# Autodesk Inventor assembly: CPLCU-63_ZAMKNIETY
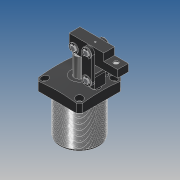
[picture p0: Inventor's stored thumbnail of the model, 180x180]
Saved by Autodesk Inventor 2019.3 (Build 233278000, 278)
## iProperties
Created: 2010-03
Part Number: CPLCU-63_ZAMKNIETY
Material: Ogólny
Document SubType Name: Assembly
Designer: CADENGINEERING4
Sending System: PRO/ENGINEER BY PARAMETRIC TECHNOLOGY CORPORATION, 2007170
Preprocessor: PRO/ENGINEER BY PARAMETRIC TECHNOLOGY CORPORATION, 2007170
Title: CPLCU-63_ASM
Author: Administrator
Revision Number: 6LAST_VERSION
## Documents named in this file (10)
- E:\SERWER_ZAPAS\MODELE brakujace\PNEUMATIC\CPLCU(STEP)\cplcu-63_asm\CPLCU-63_ZAMKNIETY.iam
- E:\SERWER_ZAPAS\MODELE brakujace\PNEUMATIC\CPLCU(STEP)\cplcu-63_asm\CPLCU-63-07.ipt
- E:\SERWER_ZAPAS\MODELE brakujace\PNEUMATIC\CPLCU(STEP)\cplcu-63_asm\CPLCU-63-06.ipt
- E:\SERWER_ZAPAS\MODELE brakujace\PNEUMATIC\CPLCU(STEP)\cplcu-63_asm\CPLCU-63-05.ipt
- E:\SERWER_ZAPAS\MODELE brakujace\PNEUMATIC\CPLCU(STEP)\cplcu-63_asm\CPLCU-63-01.ipt
- E:\SERWER_ZAPAS\MODELE brakujace\PNEUMATIC\CPLCU(STEP)\cplcu-63_asm\CPLCU-63-02.ipt
- E:\SERWER_ZAPAS\MODELE brakujace\PNEUMATIC\CPLCU(STEP)\cplcu-63_asm\CPLCU-63-08.ipt
- E:\SERWER_ZAPAS\MODELE brakujace\PNEUMATIC\CPLCU(STEP)\cplcu-63_asm\CPLCU-63-03.ipt
- E:\SERWER_ZAPAS\MODELE brakujace\PNEUMATIC\CPLCU(STEP)\cplcu-63_asm\CPLCU-63-04.ipt
- E:\SERWER_ZAPAS\MODELE brakujace\PNEUMATIC\CPLCU(STEP)\cplcu-63_asm\CPLCU-50-08.ipt
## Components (21 placed, 21 different names)
1. CPLCU-63-07_0 — Zestawiające:22
2. CPLCU-63-06_1 — Zestawiające:13, Zestawiające:14, Zestawiające:15, Zestawiające:16, Zestawiające:20, Zestawiające:22
3. CPLCU-63-05_2 — Zestawiające:1, Zestawiające:2, Zestawiające:5, Zestawiające:6, Kątowe:1
4. CPLCU-63-01_3 — Zestawiające:23, Zestawiające:24, Zestawiające:25, Kątowe:1
5. CPLCU-63-02_4 — Zestawiające:3, Zestawiające:4, Zestawiające:5, Zestawiające:12, Zestawiające:24
6. CPLCU-63-02_5 — Zestawiające:3, Zestawiające:4, Zestawiające:6, Zestawiające:7
7. CPLCU-63-08_6 — Zestawiające:14, Zestawiające:15, Zestawiające:19, Zestawiające:21
8. CPLCU-63-08_7 — Zestawiające:2, Zestawiające:9
9. CPLCU-63-08_8 — Zestawiające:7
10. CPLCU-63-08_9 — Zestawiające:13, Zestawiające:16, Zestawiające:17, Zestawiające:18, Zestawiające:25
11. CPLCU-63-08_10
12. CPLCU-63-08_11 — Zestawiające:1, Zestawiające:8
13. CPLCU-63-03_12 — Równoległe:4, Równoległe:5, Zestawiające:20
14. CPLCU-63-04_13 — Równoległe:1, Zestawiające:8, Zestawiające:9, Zestawiające:10, Zestawiające:11, Zestawiające:12, Zestawiające:23
15. CPLCU-63-04_14 — Równoległe:1
16. CPLCU-50-08_15 — Równoległe:5, Zestawiające:19, Zestawiające:21
17. CPLCU-50-08_16 — Równoległe:4, Zestawiające:17, Zestawiające:18
18. CPLCU-50-08_17 — Równoległe:3, Zestawiające:11
19. CPLCU-50-08_18 — Równoległe:3
20. CPLCU-50-08_19 — Równoległe:2, Zestawiające:10
21. CPLCU-50-08_20 — Równoległe:2
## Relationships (31: Mate 25, Flush 5, Angle 1)
- Równoległe:1 [Flush]: CPLCU-63-04_13 ↔ CPLCU-63-04_14
- Równoległe:2 [Flush]: CPLCU-50-08_19 ↔ CPLCU-50-08_20
- Równoległe:3 [Flush]: CPLCU-50-08_17 ↔ CPLCU-50-08_18
- Zestawiające:1 [Mate]: CPLCU-63-05_2 ↔ CPLCU-63-08_11
- Zestawiające:2 [Mate]: CPLCU-63-05_2 ↔ CPLCU-63-08_7
- Zestawiające:3 [Mate]: CPLCU-63-02_4 ↔ CPLCU-63-02_5
- Zestawiające:4 [Mate]: CPLCU-63-02_4 ↔ CPLCU-63-02_5
- Zestawiające:5 [Mate]: CPLCU-63-05_2 ↔ CPLCU-63-02_4
- Zestawiające:6 [Mate]: CPLCU-63-05_2 ↔ CPLCU-63-02_5
- Zestawiające:7 [Mate]: CPLCU-63-02_5 ↔ CPLCU-63-08_8
- Zestawiające:8 [Mate]: CPLCU-63-08_11 ↔ CPLCU-63-04_13
- Zestawiające:9 [Mate]: CPLCU-63-08_7 ↔ CPLCU-63-04_13
- Zestawiające:10 [Mate]: CPLCU-63-04_13 ↔ CPLCU-50-08_19
- Zestawiające:11 [Mate]: CPLCU-63-04_13 ↔ CPLCU-50-08_17
- Zestawiające:12 [Mate]: CPLCU-63-02_4 ↔ CPLCU-63-04_13
- Równoległe:4 [Flush]: CPLCU-63-03_12 ↔ CPLCU-50-08_16
- Równoległe:5 [Flush]: CPLCU-63-03_12 ↔ CPLCU-50-08_15
- Zestawiające:13 [Mate]: CPLCU-63-06_1 ↔ CPLCU-63-08_9
- Zestawiające:14 [Mate]: CPLCU-63-06_1 ↔ CPLCU-63-08_6
- Zestawiające:15 [Mate]: CPLCU-63-06_1 ↔ CPLCU-63-08_6
- Zestawiające:16 [Mate]: CPLCU-63-06_1 ↔ CPLCU-63-08_9
- Zestawiające:17 [Mate]: CPLCU-63-08_9 ↔ CPLCU-50-08_16
- Zestawiające:18 [Mate]: CPLCU-63-08_9 ↔ CPLCU-50-08_16
- Zestawiające:19 [Mate]: CPLCU-63-08_6 ↔ CPLCU-50-08_15
- Zestawiające:20 [Mate]: CPLCU-63-06_1 ↔ CPLCU-63-03_12
- Zestawiające:21 [Mate]: CPLCU-63-08_6 ↔ CPLCU-50-08_15
- Zestawiające:22 [Mate]: CPLCU-63-07_0 ↔ CPLCU-63-06_1
- Zestawiające:23 [Mate]: CPLCU-63-01_3 ↔ CPLCU-63-04_13
- Zestawiające:24 [Mate]: CPLCU-63-01_3 ↔ CPLCU-63-02_4
- Zestawiające:25 [Mate]: CPLCU-63-01_3 ↔ CPLCU-63-08_9
- Kątowe:1 [Angle]: CPLCU-63-05_2 ↔ CPLCU-63-01_3
